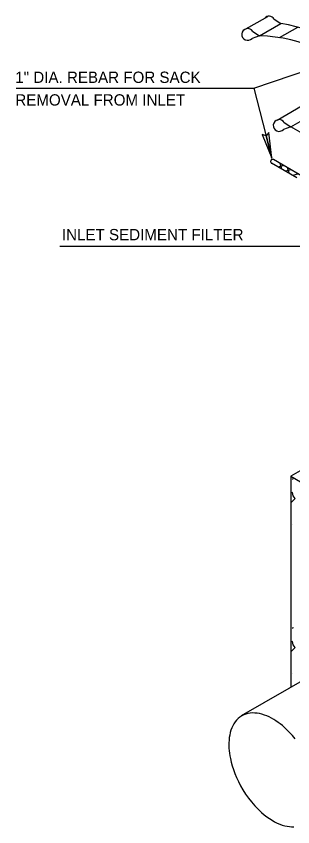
# Model space of a CAD drawing. Extents: x -120.7 to -50.3, y -20.2 to 3.8.
# Drawn here: x -80.65 to -77.72, y -9.28 to -0.69 of the extents above; entities that cross this region are included whole.
import ezdxf

# ---------------------------------------------------------------- set-up
doc = ezdxf.new("R2010")
doc.units = 0
for name, color, linetype in [('Default', 7, 'Continuous'), ('HATCH', 7, 'Continuous'), ('PR_Dimensions', 7, 'Continuous'), ('PR_Pattern_Area', 7, 'Continuous'), ('TYP_Typical_Section_Linework', 7, 'Continuous'), ('TYP_Typical_Section_Txt', 7, 'Continuous')]:
    doc.layers.add(name, color=color, linetype=linetype)

# ---------------------------------------------------------------- blocks, each defined once
blk = doc.blocks.new('ISOSACK_1')
at = {"layer": 'HATCH'}
for p, q in [((1501678.61, 358152.61), (1501678.58, 358152.94)), ((1501679.13, 358153.59), (1501678.93, 358153.57))]:
    blk.add_line(p, q, dxfattribs=at)
blk = doc.blocks.new('AR32_1')
at = {"layer": 'Default'}
for p, q in [((0, 0), (-11.43, 1.6)), ((-11.43, 1.6), (-10.39, -0.01)), ((-11.42, -1.63), (0, 0)), ((-10.39, -0.01), (-11.42, -1.63))]:
    blk.add_line(p, q, dxfattribs=at)

msp = doc.modelspace()

# ---------------------------------------------------------------- linework, layer by layer
at = {"layer": 'PR_Dimensions'}
for p, q in [((-78.1306, -1.4491), (-77.2709, -1.1579)), ((-80.649, -1.4491), (-78.1306, -1.4491)), ((-78.1306, -1.4491), (-77.937, -2.1899)), ((-78.0425, -1.9386), (-77.937, -2.1899)), ((-77.9994, -1.9525), (-78.0425, -1.9386)), ((-77.9688, -1.9192), (-77.9992, -1.9522)), ((-77.937, -2.1899), (-77.9991, -1.9525)), ((-77.937, -2.1899), (-77.9688, -1.9192)), ((-80.1873, -3.1219), (-77.1598, -3.1219))]:
    msp.add_line(p, q, dxfattribs=at)
for points in [[(-77.9991, -1.9525), (-77.9994, -1.9525)], [(-77.9992, -1.9522), (-77.9991, -1.9525), (-77.937, -2.1899)]]:
    msp.add_lwpolyline(points, dxfattribs=at)
at = {"layer": 'PR_Pattern_Area'}
for p, q in [((-77.716, -5.5833), (-77.7181, -5.5943)), ((-77.7182, -6.0715), (-77.7203, -6.0737)), ((-77.716, -7.1624), (-77.7181, -7.1733)), ((-77.7182, -7.6506), (-77.7203, -7.6528))]:
    msp.add_line(p, q, dxfattribs=at)
for points in [[(-77.7376, -5.8443), (-77.6917, -5.7972), (-77.7106, -5.7695), (-77.7209, -5.7337), (-77.7376, -5.7423)], [(-77.7376, -7.4234), (-77.6917, -7.3763), (-77.7106, -7.3486), (-77.7209, -7.3127), (-77.7376, -7.3213)]]:
    msp.add_lwpolyline(points, dxfattribs=at)
at = {"layer": 'TYP_Typical_Section_Linework'}
for p, q in [((-78.2391, -0.8359), (-77.9813, -0.6877)), ((-78.0699, -0.8925), (-77.8436, -0.7618)), ((-77.9142, -0.7167), (-77.8436, -0.7618)), ((-78.1406, -0.8474), (-78.0699, -0.8925)), ((-77.8564, -0.9136), (-77.6638, -0.8024)), ((-78.0699, -0.8925), (-78.1484, -0.922)), ((-77.8804, -1.7892), (-77.3987, -1.5047)), ((-77.7364, -1.8574), (-77.2411, -1.5714)), ((-77.7364, -1.8574), (-77.8149, -1.8869)), ((-77.8071, -1.8123), (-77.7364, -1.8574)), ((-74.9496, -3.4664), (-77.7364, -1.8574)), ((-77.6292, -2.3728), (-77.9195, -2.2052)), ((-77.6739, -2.3987), (-77.9422, -2.2438)), ((-77.8111, -2.2678), (-77.8722, -2.2842)), ((-77.8335, -2.3065), (-77.8498, -2.2454)), ((-77.7336, -2.3125), (-77.7947, -2.3289)), ((-77.756, -2.3513), (-77.7724, -2.2902)), ((-77.6561, -2.3573), (-77.7172, -2.3737)), ((-75.937, -4.5219), (-77.7376, -5.5615)), ((-77.7376, -5.5615), (-75.3126, -6.9615)), ((-77.7376, -5.5615), (-77.7376, -7.7964)), ((-78.2584, -8.0971), (-77.0203, -7.3823))]:
    msp.add_line(p, q, dxfattribs=at)
for points in [[(-77.9179, -2.2061), (-77.9217, -2.2042), (-77.9262, -2.203), (-77.9309, -2.2027), (-77.9357, -2.2036), (-77.9401, -2.2055), (-77.944, -2.2083), (-77.947, -2.2117), (-77.9492, -2.2155), (-77.9506, -2.2196), (-77.9512, -2.2242), (-77.9509, -2.2291), (-77.9495, -2.234), (-77.9471, -2.2385), (-77.9439, -2.2423), (-77.9403, -2.2451), (-77.9364, -2.2471)], [(-77.692, -8.3424), (-77.7206, -8.3082), (-77.7493, -8.2767), (-77.7778, -8.248), (-77.8059, -8.2219), (-77.8269, -8.2039), (-77.8486, -8.1865), (-77.8711, -8.1698), (-77.8942, -8.1539), (-77.918, -8.139), (-77.9423, -8.1251), (-77.967, -8.1125), (-77.9922, -8.1013), (-78.0176, -8.0916), (-78.0431, -8.0836), (-78.0687, -8.0773), (-78.0942, -8.0729), (-78.1194, -8.0705), (-78.1442, -8.0702), (-78.1685, -8.072), (-78.192, -8.0759), (-78.2148, -8.0821), (-78.2365, -8.0905), (-78.2572, -8.101), (-78.2767, -8.1136), (-78.2948, -8.1283), (-78.3115, -8.1449), (-78.3267, -8.1633), (-78.3404, -8.1835), (-78.3525, -8.2051), (-78.3631, -8.2282), (-78.372, -8.2524), (-78.3794, -8.2777), (-78.3852, -8.3038), (-78.3895, -8.3307), (-78.3923, -8.3581), (-78.3938, -8.3858), (-78.394, -8.4138), (-78.3929, -8.4418), (-78.3907, -8.4698), (-78.3875, -8.4976), (-78.3832, -8.5251), (-78.3781, -8.5523), (-78.3696, -8.5897), (-78.359, -8.6288), (-78.3461, -8.6693), (-78.3307, -8.7112), (-78.3129, -8.7541), (-78.2926, -8.7977), (-78.2697, -8.8418), (-78.2443, -8.8858), (-78.2164, -8.9294), (-78.1863, -8.972), (-78.1541, -9.0133), (-78.1201, -9.0528), (-78.0845, -9.09), (-78.0478, -9.1245), (-78.0202, -9.1479), (-77.9922, -9.1696), (-77.9642, -9.1894), (-77.9361, -9.2072), (-77.9083, -9.223), (-77.8807, -9.2367), (-77.8536, -9.2483), (-77.8271, -9.2578), (-77.8013, -9.2653), (-77.7763, -9.2708), (-77.7521, -9.2744), (-77.7289, -9.2761), (-77.7067, -9.2761)]]:
    msp.add_lwpolyline(points, dxfattribs=at)
for centre, radius, start, end in [((-77.9679, -0.7487), 0.0625, 30.8699, 137.35862), ((-78.1364, -2.4792), 1.7421, 355.08054, 80.32246), ((-78.1942, -0.8794), 0.0625, 30.8699, 317.1301), ((-78.1273, -2.5675), 1.676, 359.25967, 88.03722), ((-77.8607, -1.8443), 0.0625, 30.8699, 317.1301)]:
    msp.add_arc(centre, radius, start, end, dxfattribs=at)

# ---------------------------------------------------------------- block references
at = {"layer": 'PR_Dimensions', "xscale": 0.02362199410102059, "yscale": 0.023621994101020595, "rotation": -75.35607824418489}
msp.add_blockref('AR32_1', (-77.937, -2.1899), dxfattribs=at)
at = {"layer": 'PR_Pattern_Area', "xscale": 0.015747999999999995, "yscale": 0.015747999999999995}
msp.add_blockref('ISOSACK_1', (-23726.1605, -5642.0509), dxfattribs=at)

# ---------------------------------------------------------------- texts
at = {"layer": 'TYP_Typical_Section_Txt'}
for s, p in [('1" DIA. REBAR FOR SACK', (-80.6584, -1.3934)), ('REMOVAL FROM INLET', (-80.6584, -1.6334)), ('INLET SEDIMENT FILTER', (-80.1644, -3.0609))]:
    msp.add_text(s, height=0.12, dxfattribs=at).set_placement(p)

doc.saveas('drawing.dxf')
